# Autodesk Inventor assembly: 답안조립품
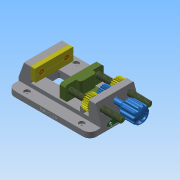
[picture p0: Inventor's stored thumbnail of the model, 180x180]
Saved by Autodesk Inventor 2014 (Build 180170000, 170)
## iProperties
Created: 2018-03
Part Number: 답안조립품
Document SubType Name: Assembly
Designer: net
Mass: 1443.92 g
Surface Area: 918.509 cm^2
Volume: 340.421 cm^3
Density: 4.24156 g/cm^3
Author: net
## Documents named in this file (10)
- C:\Users\net\Desktop\380307V1014\답안조립품.iam
- C:\Users\net\Desktop\380307V1014\바이스본체 A.ipt
- C:\Users\net\Desktop\380307V1014\고정 플레이트.ipt
- C:\Users\net\Desktop\380307V1014\바이스본체 B.ipt
- C:\Users\net\Desktop\380307V1014\스퍼기어.ipt
- C:\Users\net\Desktop\380307V1014\슬라이딩 부품.ipt
- C:\Users\net\Desktop\380307V1014\십자오목머리나사 M3.ipt
- C:\Users\net\Desktop\380307V1014\십자오목머리나사 M4.ipt
- C:\Users\net\Desktop\380307V1014\지지대.ipt
- C:\Users\net\Desktop\380307V1014\핸들.ipt
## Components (3 placed, 2 different names)
1. 고정 플레이트:1
2. 핸들:1 — 플러쉬:16, 각도:3
3. 고정 플레이트:2
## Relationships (2: Flush 1, Angle 1)
- 플러쉬:16 [Flush]: 핸들:1
- 각도:3 [Angle]: 핸들:1
